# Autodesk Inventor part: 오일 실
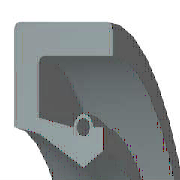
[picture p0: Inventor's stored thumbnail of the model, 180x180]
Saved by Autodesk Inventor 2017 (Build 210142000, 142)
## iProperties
IsCustomPart: 0
Created: 2016-05
Part Number: 오일 실
Material: 고무
Description: 오일-실
Document SubType Name: Modeling
Standard: KS B 2804
Designer: mduedu
Standards Organization: KS
Language: ko-KR
Size Designation: S - 17 30 8
Categories: <MemberInstance><Categories><Category DisplayName="샤프트 부품" InternalName="7f7aeb1f-a693-4053-b835-cee3144e0d98" Mnemonic="SHFT"><Category DisplayName="실링" Intern
Density: 0.93 g/cm^3
Appearance: 고무 - 검은색 - 버전 1.1
Author: mduedu
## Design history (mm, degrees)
revolve "본체" stored, may be unused: angle "d17" = 90 deg
revolve "스프링1" stored, may be unused: angle "d18" = 90 deg
body "Solid1"
sketch "스케치1"
  geometry: L1 (0, 15)-(8, 15); L2 (8, 15)-(8, 13.75); L3 (8, 13.75)-(1.75, 13.75); L4 (0, 15)-(0, 10.6); L5 (0, 10.6)-(1.75, 10.25); L6 (1.75, 10.25)-(4.9, 8.5); L7 (4.9, 8.5)-(0, 8.5); L8 (6.3, 9.375)-(6.3, 10.6); L9 (0, 0)-(9.586, 0) reference; L10 (4.9, 8.5)-(6.3, 9.375); L11 (0, 18)-(0, -3) reference; L12 (-1.917, 0)-(11.503, 0) reference; L13 (4.2, 10.6)-(1.75, 11.09); L14 (1.75, 11.09)-(1.75, 13.75); L15 (6.3, 10.6)-(5.6, 10.6); C1 r 0.455 at (4.9, 10.6); A1 r 0.7 centre (4.9, 10.6) between (5.6, 10.6) and (4.2, 10.6)
  constraints: 26 end point, 5 horizontal alignment, 4 perpendicular, 2 centre point, 2 collinear, 2 horizontal, 2 parallel, 2 point on circle, 2 point on line, 2 vertical alignment, 1 coincident
  dimensions: "d0" = 30 diameter of L1 L9 (= SD2); "d1" = 18.75 diameter of L8.start L9 (= ABDM); "d2" = 1.25 distance of L1.end L2.end (computed from SD); "d3" = 0.91 diameter of C1 (= SPDI); "d4" = 1.4 diameter of A1 (= SPDA); "d5" = 17 diameter of L6.end L9 (= NND); "d6" = 20.5 diameter of L5.end L9 (= TKDM); "d7" = 21.2 diameter of L4.end L9 (= HLDM); "d8" = 4.9 distance from line of C1.centre L4 (= SPDST); "d9" = 6.3 distance between parallel lines of L8 L4 (= SDI); "d10" = 8 distance between parallel lines of L2 L4 (= SWDT); "d12" = 1.75 distance between parallel lines of L14 L4 (= SD)
fillet "모깎기1" dims "d11" = 0.3 (= RR)
other parameters: "SD2" = 30 [user parameter; used in 1 equation term], "SWDT" = 8 [user parameter; used in 1 equation term], "RR" = 0.3 [user parameter; used in 1 equation term], "SD" = 1.75 [user parameter; used in 2 equation terms], "NND" = 17 [user parameter; used in 1 equation term], "SPDA" = 1.4 [user parameter; used in 1 equation term], "SPDI" = 0.91 [user parameter; used in 1 equation term], "TKDM" = 20.5 [user parameter; used in 1 equation term], "HLDM" = 21.2 [user parameter; used in 1 equation term], "ABDM" = 18.75 [user parameter; used in 1 equation term], "SDI" = 6.3 [user parameter; used in 1 equation term], "SPDST" = 4.9 [user parameter; used in 1 equation term], "d13" = 0, "d14" = 0, "d15" = 0, "LAB" = 0.35 [user parameter]
